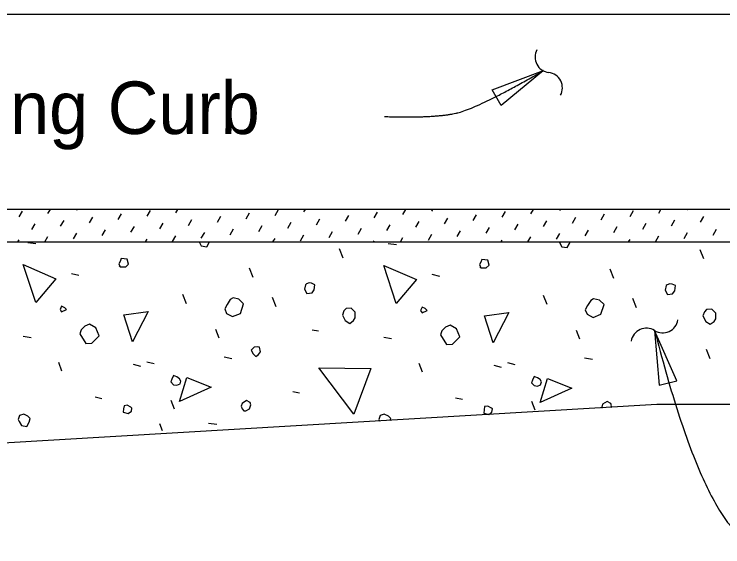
# Model space of a CAD drawing. Extents: x 21587 to 21656.3, y 56114 to 56157.2.
# Drawn here: x 21596.712 to 21599.433, y 56132.755 to 56134.801 of the extents above; entities that cross this region are included whole.
import ezdxf

# ---------------------------------------------------------------- set-up
doc = ezdxf.new("R2010")
doc.units = 0
for name, color, linetype in [('AdhocPoint_dp', 7, 'Continuous'), ('PlotBorder_dp', 7, 'Continuous'), ('SheetBorder_dp', 7, 'Continuous'), ('TextMisc', 7, 'Continuous')]:
    doc.layers.add(name, color=color, linetype=linetype)

msp = doc.modelspace()

# ---------------------------------------------------------------- linework, layer by layer
at = {"layer": 'AdhocPoint_dp'}
for p, q in [((21593.9596, 56134.8009), (21601.9067, 56134.8009)), ((21604.323, 56134.0511), (21593.9596, 56134.0511)), ((21593.9596, 56133.926), (21604.323, 56133.926)), ((21599.1795, 56133.301), (21594.9596, 56133.051)), ((21604.323, 56133.301), (21599.1795, 56133.301))]:
    msp.add_line(p, q, dxfattribs=at)
at = {"layer": 'PlotBorder_dp'}
for points in [[(21598.7452, 56134.5845), (21598.5825, 56134.4497), (21598.5472, 56134.5108)], [(21599.1716, 56133.5858), (21599.1887, 56133.3753), (21599.257, 56133.3927)]]:
    msp.add_lwpolyline(points, close=True, dxfattribs=at)
for centre, start, end in [((21598.7718, 56134.636), 151.5267, 263.2539), ((21598.7578, 56134.5176), 331.5267, 83.2539), ((21599.2025, 56133.6363), 238.4384, 350.1656), ((21599.1401, 56133.5347), 58.4384, 170.1656)]:
    msp.add_arc(centre, 0.0596, start, end, dxfattribs=at)
for points in [[(21598.1343, 56134.4076), (21598.3174, 56134.4019), (21598.4885, 56134.4362), (21598.7452, 56134.5845)], [(21599.172, 56133.5857), (21599.3832, 56132.7545), (21599.5945, 56132.7545)]]:
    msp.add_open_spline(points, degree=2, dxfattribs=at)
at = {"layer": 'TextMisc'}
for p, q in [((21596.7309, 56134.0219), (21596.7438, 56134.0443)), ((21596.8415, 56134.0349), (21596.8509, 56134.0511)), ((21596.9521, 56134.0479), (21596.954, 56134.0511)), ((21597.2222, 56134.0249), (21597.2352, 56134.0473)), ((21597.3329, 56134.0379), (21597.3405, 56134.0511)), ((21597.4435, 56134.0509), (21597.4436, 56134.0511)), ((21597.7136, 56134.028), (21597.7266, 56134.0504)), ((21597.8242, 56134.0409), (21597.8301, 56134.0511)), ((21598.205, 56134.031), (21598.2166, 56134.0511)), ((21598.3156, 56134.044), (21598.3197, 56134.0511)), ((21598.5857, 56134.021), (21598.5987, 56134.0434)), ((21598.6963, 56134.034), (21598.7062, 56134.0511)), ((21598.807, 56134.047), (21598.8094, 56134.0511)), ((21599.0771, 56134.0241), (21599.09, 56134.0465)), ((21599.1877, 56134.037), (21599.1958, 56134.0511)), ((21599.2983, 56134.05), (21599.299, 56134.0511)), ((21597.001, 56133.999), (21597.0139, 56134.0214)), ((21597.1116, 56134.012), (21597.1246, 56134.0344)), ((21597.4923, 56134.002), (21597.5053, 56134.0244)), ((21597.603, 56134.015), (21597.6159, 56134.0374)), ((21597.8731, 56133.9921), (21597.886, 56134.0145)), ((21597.9837, 56134.0051), (21597.9967, 56134.0275)), ((21598.0943, 56134.018), (21598.1073, 56134.0404)), ((21598.3644, 56133.9951), (21598.3774, 56134.0175)), ((21598.4751, 56134.0081), (21598.488, 56134.0305)), ((21598.8558, 56133.9981), (21598.8688, 56134.0205)), ((21598.9664, 56134.0111), (21598.9794, 56134.0335)), ((21599.3472, 56134.0012), (21599.3601, 56134.0235)), ((21596.7797, 56133.9731), (21596.7927, 56133.9955)), ((21596.8903, 56133.9861), (21596.9033, 56134.0084)), ((21597.2711, 56133.9761), (21597.284, 56133.9985)), ((21597.3817, 56133.9891), (21597.3947, 56134.0115)), ((21597.6518, 56133.9662), (21597.6648, 56133.9886)), ((21597.7624, 56133.9791), (21597.7754, 56134.0015)), ((21598.1432, 56133.9692), (21598.1561, 56133.9916)), ((21598.2538, 56133.9822), (21598.2668, 56134.0045)), ((21598.6345, 56133.9722), (21598.6475, 56133.9946)), ((21598.7452, 56133.9852), (21598.7581, 56134.0076)), ((21599.1259, 56133.9752), (21599.1389, 56133.9976)), ((21599.2365, 56133.9882), (21599.2495, 56134.0106)), ((21597.0498, 56133.9502), (21597.0628, 56133.9726)), ((21597.1604, 56133.9631), (21597.1734, 56133.9855)), ((21597.4305, 56133.9402), (21597.4435, 56133.9626)), ((21597.5412, 56133.9532), (21597.5541, 56133.9756)), ((21597.9219, 56133.9433), (21597.9349, 56133.9657)), ((21598.0325, 56133.9562), (21598.0455, 56133.9786)), ((21598.4133, 56133.9463), (21598.4262, 56133.9687)), ((21598.5239, 56133.9592), (21598.5369, 56133.9816)), ((21598.9046, 56133.9493), (21598.9176, 56133.9717)), ((21599.0153, 56133.9623), (21599.0282, 56133.9847)), ((21599.2854, 56133.9394), (21599.2983, 56133.9617)), ((21599.396, 56133.9523), (21599.409, 56133.9747)), ((21596.7264, 56133.926), (21596.7309, 56133.9337)), ((21596.8296, 56133.926), (21596.8415, 56133.9466)), ((21596.9392, 56133.9372), (21596.9521, 56133.9596)), ((21597.2161, 56133.926), (21597.2222, 56133.9367)), ((21597.3199, 56133.9273), (21597.3329, 56133.9497)), ((21597.7057, 56133.926), (21597.7136, 56133.9397)), ((21597.8113, 56133.9303), (21597.8242, 56133.9527)), ((21598.1953, 56133.926), (21598.205, 56133.9427)), ((21598.3026, 56133.9333), (21598.3156, 56133.9557)), ((21598.5818, 56133.926), (21598.5857, 56133.9328)), ((21598.6849, 56133.926), (21598.6963, 56133.9458)), ((21598.794, 56133.9363), (21598.807, 56133.9587)), ((21599.0714, 56133.926), (21599.0771, 56133.9358)), ((21599.1747, 56133.9264), (21599.1877, 56133.9488)), ((21596.7639, 56133.9236), (21596.7957, 56133.9201)), ((21597.6025, 56133.926), (21597.603, 56133.9268)), ((21598.0922, 56133.926), (21598.0943, 56133.9298)), ((21598.1485, 56133.9201), (21598.1804, 56133.9165)), ((21597.9759, 56133.8641), (21597.9618, 56133.8995)), ((21599.3606, 56133.8606), (21599.3465, 56133.8959)), ((21597.6301, 56133.7892), (21597.6159, 56133.8246)), ((21596.9318, 56133.8051), (21596.9601, 56133.7981)), ((21598.3165, 56133.8016), (21598.3448, 56133.7945)), ((21599.0148, 56133.7857), (21599.0006, 56133.8211)), ((21597.3737, 56133.6885), (21597.3596, 56133.7238)), ((21598.7584, 56133.6849), (21598.7443, 56133.7203)), ((21597.7178, 56133.6767), (21597.7037, 56133.7121)), ((21599.1025, 56133.6732), (21599.0884, 56133.7085)), ((21597.4993, 56133.5559), (21597.4869, 56133.5895)), ((21597.8557, 56133.5883), (21597.8805, 56133.5848)), ((21598.8839, 56133.5524), (21598.8716, 56133.5859)), ((21596.7468, 56133.5636), (21596.7769, 56133.5583)), ((21598.1315, 56133.5601), (21598.1615, 56133.5547)), ((21599.3845, 56133.4774), (21599.3704, 56133.5127)), ((21597.5181, 56133.484), (21597.5481, 56133.4787)), ((21598.9028, 56133.4805), (21598.9328, 56133.4752)), ((21596.8953, 56133.4292), (21596.8829, 56133.4628)), ((21597.1693, 56133.4558), (21597.1976, 56133.4487)), ((21597.2217, 56133.4657), (21597.25, 56133.4587)), ((21598.28, 56133.4257), (21598.2676, 56133.4593)), ((21598.554, 56133.4522), (21598.5823, 56133.4451)), ((21598.6064, 56133.4622), (21598.6347, 56133.4551)), ((21597.7815, 56133.3515), (21597.808, 56133.3462)), ((21597.0226, 56133.3302), (21597.0491, 56133.3249)), ((21597.3278, 56133.2831), (21597.3154, 56133.3167)), ((21598.4073, 56133.3267), (21598.4338, 56133.3214)), ((21598.7125, 56133.2796), (21598.7001, 56133.3132)), ((21597.2818, 56133.2001), (21597.2712, 56133.2267)), ((21597.458, 56133.2295), (21597.4898, 56133.2259))]:
    msp.add_line(p, q, dxfattribs=at)
for points in [[(21597.4221, 56133.926), (21597.4303, 56133.9112), (21597.4515, 56133.9077), (21597.4604, 56133.9236), (21597.461, 56133.926)], [(21598.8049, 56133.926), (21598.8062, 56133.9236)], [(21598.8062, 56133.9236), (21598.815, 56133.9077), (21598.8362, 56133.9041), (21598.845, 56133.9201), (21598.8465, 56133.926)], [(21597.1192, 56133.8299), (21597.1404, 56133.8299), (21597.151, 56133.8405), (21597.1457, 56133.8599), (21597.1227, 56133.8617), (21597.1192, 56133.8511), (21597.1139, 56133.8423), (21597.1192, 56133.8299), (21597.1157, 56133.8334)], [(21598.5039, 56133.8264), (21598.5251, 56133.8264), (21598.5357, 56133.837), (21598.5304, 56133.8564), (21598.5074, 56133.8582), (21598.5039, 56133.8476), (21598.4986, 56133.8387), (21598.5039, 56133.8264), (21598.5003, 56133.8299)], [(21596.7945, 56133.6926), (21596.7468, 56133.8394), (21596.8723, 56133.7846), (21596.7945, 56133.6926)], [(21598.1792, 56133.6891), (21598.1315, 56133.8358), (21598.257, 56133.781), (21598.1792, 56133.6891)], [(21597.8274, 56133.7439), (21597.8363, 56133.728), (21597.8557, 56133.7298), (21597.8646, 56133.7421), (21597.8663, 56133.7616), (21597.854, 56133.7669), (21597.8451, 56133.7686), (21597.8345, 56133.7651), (21597.831, 56133.7616), (21597.8274, 56133.7439)], [(21599.2121, 56133.7404), (21599.221, 56133.7245), (21599.2404, 56133.7262), (21599.2492, 56133.7386), (21599.251, 56133.758), (21599.2386, 56133.7633), (21599.2298, 56133.7651), (21599.2192, 56133.7616), (21599.2156, 56133.758), (21599.2121, 56133.7404)], [(21597.5275, 56133.6514), (21597.5505, 56133.639), (21597.5806, 56133.6514), (21597.593, 56133.6885), (21597.5753, 56133.7062), (21597.5523, 56133.7115), (21597.5417, 56133.7044), (21597.5293, 56133.6849), (21597.5205, 56133.669), (21597.5275, 56133.6514)], [(21598.9122, 56133.6478), (21598.9352, 56133.6354), (21598.9653, 56133.6478), (21598.9776, 56133.6849), (21598.9599, 56133.7026), (21598.937, 56133.7079), (21598.9264, 56133.7008), (21598.914, 56133.6814), (21598.9051, 56133.6655), (21598.9122, 56133.6478)], [(21596.8935, 56133.6573), (21596.913, 56133.6661), (21596.9059, 56133.6732), (21596.8935, 56133.6785), (21596.8882, 56133.6661), (21596.8935, 56133.6573)], [(21597.9724, 56133.6449), (21597.983, 56133.6237), (21598.0007, 56133.6131), (21598.0148, 56133.6237), (21598.0219, 56133.6343), (21598.0219, 56133.6555), (21598.006, 56133.6714), (21597.9865, 56133.6697), (21597.9777, 56133.6608), (21597.9724, 56133.6449)], [(21598.2782, 56133.6537), (21598.2977, 56133.6626), (21598.2906, 56133.6697), (21598.2782, 56133.675), (21598.2729, 56133.6626), (21598.2782, 56133.6537)], [(21599.3571, 56133.6414), (21599.3677, 56133.6202), (21599.3854, 56133.6096), (21599.3995, 56133.6202), (21599.4066, 56133.6308), (21599.4066, 56133.652), (21599.3907, 56133.6679), (21599.3712, 56133.6661), (21599.3624, 56133.6573), (21599.3571, 56133.6414)], [(21597.1669, 56133.5417), (21597.1333, 56133.646), (21597.227, 56133.6584), (21597.1669, 56133.5417)], [(21598.5516, 56133.5382), (21598.518, 56133.6425), (21598.6117, 56133.6549), (21598.5516, 56133.5382)], [(21596.9643, 56133.5724), (21596.9872, 56133.5353), (21597.0102, 56133.5371), (21597.0191, 56133.5459), (21597.0385, 56133.5654), (21597.0261, 56133.5954), (21597.0014, 56133.6096), (21596.9837, 56133.6025), (21596.9696, 56133.5883), (21596.9643, 56133.5724)], [(21598.3489, 56133.5689), (21598.3719, 56133.5318), (21598.3949, 56133.5335), (21598.4037, 56133.5424), (21598.4232, 56133.5618), (21598.4108, 56133.5919), (21598.3861, 56133.606), (21598.3684, 56133.5989), (21598.3542, 56133.5848), (21598.3489, 56133.5689)], [(21597.6294, 56133.4964), (21597.6401, 56133.4858), (21597.6507, 56133.4929), (21597.6577, 56133.5035), (21597.6542, 56133.5212), (21597.6454, 56133.5229), (21597.633, 56133.5212), (21597.6224, 56133.5106), (21597.6294, 56133.4964)], [(21598.0166, 56133.2648), (21597.8822, 56133.4416), (21598.082, 56133.4398), (21598.0166, 56133.2648)], [(21597.3242, 56133.3773), (21597.3366, 56133.3756), (21597.349, 56133.3809), (21597.3525, 56133.3915), (21597.3472, 56133.4003), (21597.3366, 56133.4074), (21597.3242, 56133.4127), (21597.3172, 56133.3986), (21597.3136, 56133.388), (21597.3242, 56133.3773)], [(21597.3466, 56133.3126), (21597.3749, 56133.4045), (21597.4686, 56133.3674), (21597.3466, 56133.3126)], [(21598.7089, 56133.3738), (21598.7213, 56133.372), (21598.7337, 56133.3773), (21598.7372, 56133.388), (21598.7319, 56133.3968), (21598.7213, 56133.4039), (21598.7089, 56133.4092), (21598.7019, 56133.395), (21598.6983, 56133.3844), (21598.7089, 56133.3738)], [(21598.7313, 56133.309), (21598.7596, 56133.401), (21598.8533, 56133.3638), (21598.7313, 56133.309)], [(21597.5941, 56133.2772), (21597.6012, 56133.2772), (21597.6153, 56133.2843), (21597.6206, 56133.3002), (21597.6188, 56133.309), (21597.6047, 56133.3161), (21597.587, 56133.3055), (21597.5835, 56133.2949), (21597.587, 56133.2843), (21597.5941, 56133.2772)], [(21599.003, 56133.2899), (21599.0053, 56133.2967), (21599.0035, 56133.3055), (21598.9894, 56133.3126), (21598.9717, 56133.302), (21598.9682, 56133.2914), (21598.9693, 56133.2878)], [(21597.1304, 56133.2719), (21597.1499, 56133.2666), (21597.1622, 56133.2754), (21597.164, 56133.2878), (21597.1605, 56133.2914), (21597.1463, 56133.2984), (21597.134, 56133.2967), (21597.1322, 56133.2843), (21597.1304, 56133.2719)], [(21598.5151, 56133.2684), (21598.5345, 56133.2631), (21598.5469, 56133.2719), (21598.5487, 56133.2843), (21598.5452, 56133.2878), (21598.531, 56133.2949), (21598.5186, 56133.2931), (21598.5169, 56133.2807), (21598.5151, 56133.2684)], [(21596.7309, 56133.2366), (21596.7397, 56133.2206), (21596.761, 56133.2171), (21596.7698, 56133.233), (21596.7733, 56133.2472), (21596.7645, 56133.256), (21596.7486, 56133.2648), (21596.7327, 56133.2595), (21596.7274, 56133.2436), (21596.7309, 56133.2366)], [(21598.1564, 56133.2405), (21598.158, 56133.2471), (21598.1492, 56133.256), (21598.1333, 56133.2648), (21598.1174, 56133.2595), (21598.112, 56133.2436), (21598.1149, 56133.2379)]]:
    msp.add_lwpolyline(points, dxfattribs=at)

# ---------------------------------------------------------------- texts
at = {"layer": 'SheetBorder_dp'}
msp.add_text('Existing Curb', height=0.2016, dxfattribs=at).set_placement((21596.0521, 56134.3406))

doc.saveas('drawing.dxf')
